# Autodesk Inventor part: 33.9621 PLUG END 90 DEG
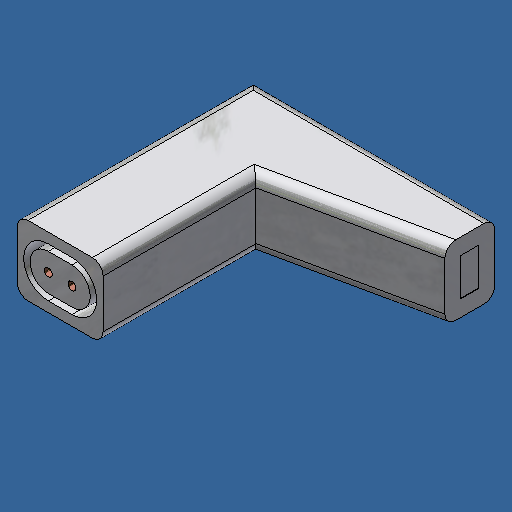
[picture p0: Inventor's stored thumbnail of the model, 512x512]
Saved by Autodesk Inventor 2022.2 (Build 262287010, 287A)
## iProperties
Created: 2017-10
Part Number: 33.9621 PLUG END 90 DEG
Material: Generic
Document SubType Name: Modeling
Designer: Admin
Density: 1 g/cm^3
Appearance: Snow
Author: Admin
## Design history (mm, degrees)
workplane "Work Plane5"
workplane "Work Plane13"
sketch "Sketch8"
  geometry: L1 (-8, -10.832)-(8, -10.832); L2 (8, -10.832)-(8, -23.832); L3 (8, -23.832)-(-8, -23.832); L4 (-8, -23.832)-(-8, -10.832); C1 r 0.75 at (-2.2, -17.332) reference; C2 r 0.75 at (2.2, -17.332) reference; 4 further points
  constraints: 8 end point, 2 midpoint, 2 parallel, 1 horizontal, 1 perpendicular, 1 vertical alignment
  dimensions: "d38" = 16 distance of L1.start L1.end; "d39" = 13 distance of L1.end L2.end
extrude "Extrusion8" new body sketch "Sketch8" distance "d40" = 34; taper "d41" = 0 deg
sketch "Sketch11"
  geometry: L1 (-6, -23.832)-(6, -23.832) reference; L2 (8, -21.832)-(8, -12.832) reference; L3 (6, -10.832)-(-6, -10.832) reference; L4 (-8, -12.832)-(-8, -21.832) reference; L5 (2.2, -12.732)-(-2.2, -12.732) reference; L6 (-2.2, -21.932)-(2.2, -21.932) reference; L7 (2.2, -20.732)-(-2.2, -20.732) reference; L8 (-2.2, -13.932)-(2.2, -13.932) reference; L9 (-2.2, -21.932)-(2.2, -21.932) reference; L10 (2.2, -12.732)-(-2.2, -12.732) reference; C1 r 0.75 at (-2.2, -17.332) reference; C2 r 0.75 at (2.2, -17.332) reference; A1 r 2 centre (-6, -21.832) between (-8, -21.832) and (-6, -23.832) reference; A2 r 2 centre (6, -21.832) between (6, -23.832) and (8, -21.832) reference; A3 r 2 centre (6, -12.832) between (8, -12.832) and (6, -10.832) reference; A4 r 2 centre (-6, -12.832) between (-6, -10.832) and (-8, -12.832) reference; A5 r 4.6 centre (2.2, -17.332) between (2.2, -21.932) and (2.2, -12.732) reference; A6 r 4.6 centre (-2.2, -17.332) between (-2.2, -12.732) and (-2.2, -21.932) reference; A7 r 3.4 centre (2.2, -17.332) between (2.2, -20.732) and (2.2, -13.932) reference; A8 r 3.4 centre (-2.2, -17.332) between (-2.2, -13.932) and (-2.2, -20.732) reference; A9 r 4.6 centre (-2.2, -17.332) between (-2.2, -12.732) and (-2.2, -21.932) reference; A10 r 4.6 centre (2.2, -17.332) between (2.2, -21.932) and (2.2, -12.732) reference; 1 further point
extrude "Extrusion11" join sketch "Sketch11" distance "d49" = 10; taper "d50" = 0 deg
sketch "Sketch12"
  geometry: L1 (16, -34)-(16, 0) reference; L2 (0, -34)-(0, 0) reference; L3 (16, 0)-(45, 0); L4 (45, 0)-(45, -9.3); L5 (45, -9.3)-(16, -15.5); L6 (16, -15.5)-(16, 0); 1 further point
  constraints: 8 end point, 1 collinear, 1 horizontal, 1 point on line, 1 vertical
  dimensions: "d52" = 45 distance from line of L3.end L2; "d53" = 9.3 distance of L3.end L4.end; "d54" = 15.5 distance from line of L5.end L3
extrude "Extrusion12" join sketch "Sketch12" distance "d55" = 13; taper "d56" = 0 deg
sketch "Sketch13"
  geometry: L1 (0, 0)-(9.3, 0) reference; L2 (9.3, 0)-(9.3, -13) reference; L3 (3, -3)-(6.3, -3); L4 (6.3, -3)-(6.3, -10); L5 (6.3, -10)-(3, -10); L6 (3, -10)-(3, -3); 5 further points
  constraints: 8 end point, 4 midpoint, 2 parallel, 1 horizontal, 1 horizontal alignment, 1 perpendicular, 1 vertical alignment
  dimensions: "d57" = 3.3 distance of L3.start L3.end; "d58" = 7 distance of L3.end L4.end
extrude "Extrusion13" cut sketch "Sketch13" distance "d59" = 0.1; taper "d60" = 0 deg
fillet "Fillet6" dims "d61" = 2
body "Solid1"
node "Projected Loop5"
